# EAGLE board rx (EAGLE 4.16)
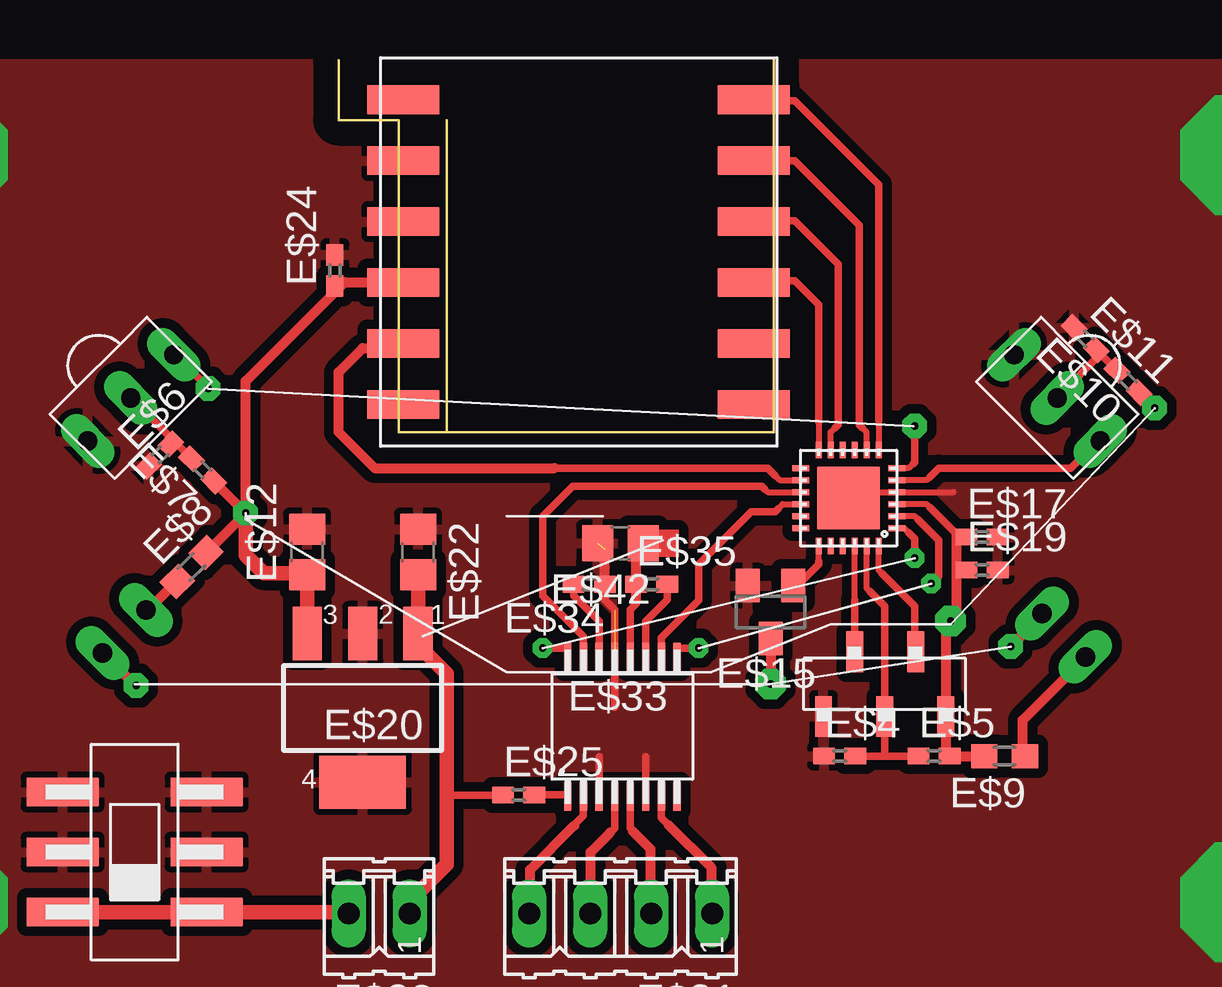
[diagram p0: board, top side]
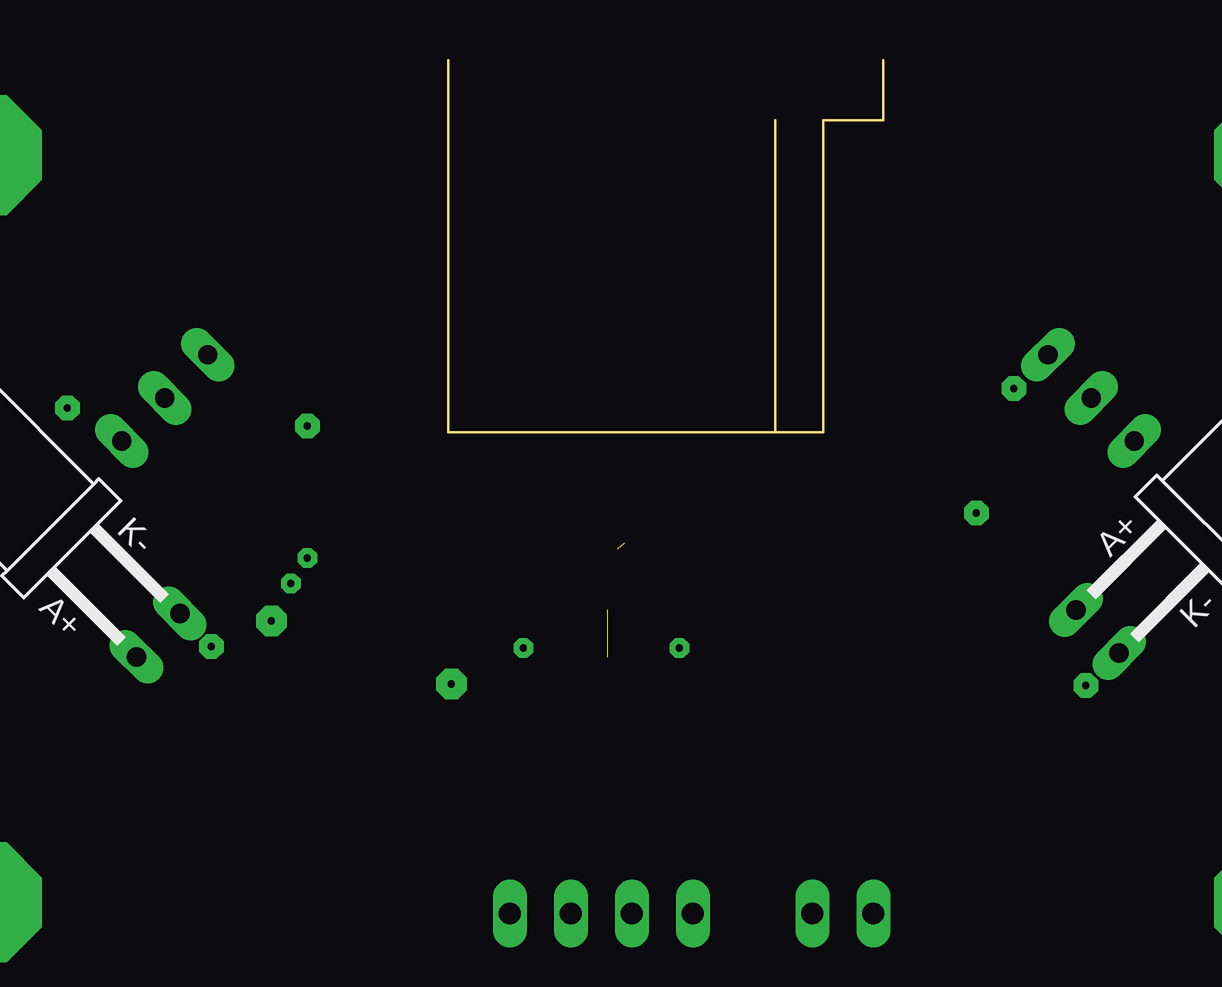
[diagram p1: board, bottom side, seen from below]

Size 18.12 x 15.5 mm. Coordinates in mm from the lower left corner, seen from the top.
Outline: 0,15.5 0,13 2.5,13 2.5,0 4.5,0
Outline: 4.5,0 18.12,0 18.12,15.5
Outline: 4.5,13 4.5,0
Copper layers (1*16): Top 0.035mm / dielectric 1.5mm / Bottom 0.035mm
Design rules "default": minimum track width 10mil, minimum drill 24mil, track to track 8mil, track to pad 8mil, pad to pad 8mil, via to via 8mil, smd to smd 8mil, copper to edge 40mil, drill to drill 8mil, minimum pad ring 10mil, minimum via ring 8mil, stop-mask expansion 4mil, vias tented up to drill 0mil, thermal gap 10mil

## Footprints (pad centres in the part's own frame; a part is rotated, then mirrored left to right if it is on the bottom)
QFN24 = smd 0.7 x 0.25: 1 -2,1.25; 2 -2,0.75; 3 -2,0.25; 4 -2,-0.25; 5 -2,-0.75; 6 -2,-1.25; 13 2,-1.25; 14 2,-0.75; 15 2,-0.25; 16 2,0.25; 17 2,0.75; 18 2,1.25 | smd 0.25 x 0.7: 7 -1.25,-2; 8 -0.75,-2; 9 -0.25,-2; 10 0.25,-2; 11 0.75,-2; 12 1.25,-2; 19 1.25,2; 20 0.75,2; 21 0.25,2; 22 -0.25,2; 23 -0.75,2; 24 -1.25,2 | smd 2.6 x 2.6: EP 0,0
ZETA-RF = smd 3 x 1.2: 1 -7.303,6.35; 2 -7.303,3.81; 3 -7.303,1.27; 4 -7.303,-1.27; 5 -7.303,-3.81; 6 -7.303,-6.35; 7 7.303,-6.35; 8 7.303,-3.81; 9 7.303,-1.27; 10 7.303,1.27; 11 7.303,3.81; 12 7.303,6.35
HEADER5S = smd 0.7 x 1.7: P$1 0,1.35; P$2 2.55,1.35; P$3 -2.55,1.35; P$4 -1.3,-1.35; P$5 1.25,-1.35
C0402 = smd 0.9 x 0.7: 1 -0.65,0; 2 0.65,0
R0603 = smd 1.1 x 1: 1 -0.85,0; 2 0.85,0
C0805 = smd 1.3 x 1.5: 1 -0.95,0; 2 0.95,0
TSOP32238 = drill 0.8 long: P$1 -2.54,0; P$2 0,0; P$3 2.54,0
SOT23 = smd 1 x 1.4: 1 -0.95,-1.1; 2 0.95,-1.1; 3 0,1.1
LED_T1 = drill 0.813 long: A -1.27,-6.35; K 1.27,-6.35
SOT223 = smd 1.219 x 2.235: 1 -2.311,-3.099; 2 0,-3.099; 3 2.311,-3.099 | smd 3.6 x 2.2: 4 0,3.099
04P = drill 0.914 long: 1 -3.81,0; 2 -1.27,0; 3 1.27,0; 4 3.81,0
02P = drill 0.914 long: 1 -1.27,0; 2 1.27,0
SLIDER5 = smd 1.2 x 3: P$1 0,3; P$2 2.5,3; P$3 -2.5,3; P$4 -2.5,-3; P$5 0,-3; P$6 2.5,-3
PW16 = smd 0.3 x 1.2: 1 0,-2.9; 2 0.65,-2.9; 3 1.3,-2.9; 4 1.95,-2.9; 5 2.6,-2.9; 6 3.25,-2.9; 7 3.9,-2.9; 8 4.55,-2.9; 13 4.55,2.9; 14 3.9,2.9; 15 3.25,2.9; 16 2.6,2.9; 17 1.95,2.9; 18 1.3,2.9; 19 0.65,2.9; 20 0,2.9

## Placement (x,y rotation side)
E$1  [QFN24]  21.25,-2.75 180 top
E$2  [ZETA-RF]  10,7.5 0 top
E$3  [HEADER5S]  not placed on the board
E$4  [C0402]  not placed on the board
E$5  [C0402]  not placed on the board
E$6  [C0402]  not placed on the board
E$7  [C0402]  not placed on the board
E$8  [R0603]  not placed on the board
E$9  [R0603]  not placed on the board
E$10  [C0402]  not placed on the board
E$11  [C0402]  not placed on the board
E$12  [C0805]  not placed on the board
E$13  [TSOP32238]  -8.66,1.42 45 top  (outside the outline)
E$14  [TSOP32238]  29.94,1.42 315 top  (outside the outline)
E$15  [SOT23]  not placed on the board
E$16  [LED_T1]  not placed on the board
E$17  [C0402]  not placed on the board
E$18  [LED_T1]  not placed on the board
E$19  [C0402]  not placed on the board
E$20  [SOT223]  not placed on the board
E$21  [04P]  not placed on the board
E$22  [C0805]  not placed on the board
E$23  [02P]  not placed on the board
E$24  [C0402]  -0.16,6.73 90 top
E$25  [C0402]  not placed on the board
E$26  [SLIDER5]  not placed on the board
E$33  [PW16]  not placed on the board
E$34  [C0402]  not placed on the board
E$35  [C0402]  not placed on the board
E$42  [C0805]  not placed on the board

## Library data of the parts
E$1 = freescale
E$2 = silabs
E$3 E$13 E$14 E$16 E$18 E$26 = sb
E$4-E$12 E$15 E$17 E$19 E$20 E$22 E$24 E$25 E$34 E$35 E$42 = ref-packages
E$21 E$23 = con-amp-quick
E$33 = TI_MSP430_v122

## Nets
GND: E$2.2 E$2.3 E$3.P$2 E$4.1 E$6.1 E$11.1 E$12.2 E$13.P$1 E$14.P$1 E$15.2 E$17.2 E$19.2 E$20.2 E$20.4 E$22.1 E$24.2 E$26.P$1 E$26.P$3 E$26.P$4 E$26.P$5 E$33.17 E$34.1 E$42.2
S$21: E$13.P$2
S$22: E$14.P$2

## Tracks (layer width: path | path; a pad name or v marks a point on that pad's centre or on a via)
GND  (via drill 0.6 pad 5)  (2 unrouted)
  Top 0.254: 22,-2.5 25.62,-2.5
  Top 0.305: 10.85,-13.53 10.85,-15.58 | 12.8,-13.53 12.8,-15.58 | 11.09,-6.83 11.09,-6.99 11.5,-7.4 11.5,-11.47
  Top 0.406: 11.09,-6.83 11.09,-4.88
  other vias: -16.28,-19.6 -16.28,11.54 37.56,-19.6 37.56,11.54
  pour Top (isolate 0.406): -20.03,-23.41 -20.03,15.35 41.37,15.35 41.37,-23.41
S$1
  Top 0.254: 20,0.44 20,-0.5
  Top 0.305: 18,6.31 19,6.31 20,5.31 20,0.44
S$2
  Top 0.254: 20.69,0.19 20.5,0 20.5,-0.5
  Top 0.305: 18,8.81 19,8.81 20.81,7 20.81,0.31 20.69,0.19
S$3
  Top 0.254: 21.81,0.19 22,0 22,-0.5
  Top 0.305: 18,11.31 19,11.31 21.69,8.62 21.69,0.31 21.81,0.19
S$4
  Top 0.254: 22.5,0.5 22.5,-0.5
  Top 0.305: 18,13.81 19,13.81 22.5,10.31 22.5,0.5
S$5
  Top 0.254: 18.19,-1.81 18.38,-2 19,-2
  Top 0.305: 9,-1.5 17.88,-1.5 18.19,-1.81
  Top 0.406: 1.5,3.5 1,3.5 0,2.5 0,0 1.5,-1.5 9,-1.5
S$6
  Top 0.254: 22.12,-6.62 22,-6.5 22,-5
  Top 0.305: 22.75,-13.5 22.75,-7.25 22.12,-6.62
S$7
  Top 0.254: 21.5,-7 21.5,-5
  Top 0.305: 21.5,-8.75 21.5,-7
S$8
  Top 0.254: 22.62,-5.88 22.5,-5.75 22.5,-5
  Top 0.305: 22.62,-5.88 24,-7.25 24,-8.75
S$9
  Top 0.305: 21.75,-13.5 23.75,-13.5
S$10
  Top 0.254: 23.5,-2 24.5,-2 24.62,-1.88 | 31.5,-0.5 31.56,-0.5
  Top 0.305: 24.62,-1.88 25,-1.5 30.5,-1.5 31.5,-0.5
S$11  (via drill 0.3 pad 1.02)
  other vias: 24,0.25
S$12
  Top 0.254: 17.75,-2.38 17.88,-2.5 19,-2.5
  Top 0.305: 10.19,-9.69 10.19,-8.5 8.5,-6.81 8.5,-3.5 9.75,-2.25 17.62,-2.25 17.75,-2.38
S$13
  Top 0.61: 3,-19.5 4.5,-18 4.5,-10.06 3.5,-9.06
S$14
  Top 0.406: 18,-9.19 18,-10.44
S$15
  Top 0.406: 28,-8.94 29.37,-7.53
S$16
  Top 0.254: 24.62,-3.12 24.5,-3 23.5,-3
  Top 0.305: 25.75,-4.25 24.62,-3.12
  Top 0.406: 25.75,-4.25 25.75,-7.62 25.31,-8.06 25.31,-13.56
S$17
  Top 0.254: 18.31,-3.19 18.5,-3 19,-3
  Top 0.305: 13.44,-9 13.44,-8.56 15,-7 15,-5.5 17.19,-3.31 18.19,-3.31 18.31,-3.19
S$18
  Top 0.305: 14.12,-9 15,-9
S$19
  Top 0.305: 8.5,-9 9.5,-9
S$20  (via drill 0.3 pad 0.81)
  other vias: 24.69,-6.31
S$21
  Top 0.305: E$13.P$2 -6.35,-0.89
S$22
  Top 0.305: E$14.P$2 31.87,3.39
S$23
  Top 0.254: 23.5,-4 23.56,-4 23.75,-4.19
  Top 0.305: 24,-5.25 24,-4.44 23.75,-4.19
S$24
  Top 0.254: 24.12,-3.62 24,-3.5 23.5,-3.5 | 25,-6 24.69,-6.31
  Top 0.305: 24.12,-3.62 25,-4.5 25,-6
S$25
  Top 0.254: 23.5,-1.5 23.75,-1.5 23.94,-1.31
  Top 0.305: 24,0.25 24,-1.25 23.94,-1.31
S$26
  Top 0.305: -5.47,1.88 -6.76,3.17
S$27
  Top 0.406: -9.8,-9.22 -8.45,-10.57
S$28  (via drill 0.3 pad 1.02)
  other vias: 28,-8.94
S$29  (via drill 0.3 pad 0.81)
  other vias: 24,-5.25
S$30  (via drill 0.3 pad 0.81)
  other vias: 15,-9
S$31  (via drill 0.3 pad 0.81)
  other vias: 8.5,-9
S$32
  Top 0.254: 20,-5.38 20,-5
  Top 0.305: 20,-5.38 20,-5.5 19,-6.5
S$33
  Top 0.406: 28.5,-13.5 28.5,-12 31,-9.5
S$34  (via drill 0.3 pad 1.27)
  other vias: 18,-10.5
S$35  (via drill 0.3 pad 1.02)
  Top 0.305: v34,1 33.5,1.5
S$36
  Top 0.406: -5.06,-2.19 -3.88,-3.38 -5.5,-5
  Top 0.61: -1.31,-7.38 -1.31,-5.88 -3.12,-5.88 -3.88,-5.12 -3.88,-3.38
S$37  (via drill 0.3 pad 1.02)
  other vias: -8.44,-10.56
S$38
  Top 0.406: -8.03,-7.47 -6.76,-6.24
S$39
  Top 0.406: 25.5,-13.5 27,-13.5
S$40  (via drill 0.3 pad 1.02)
  other vias: -3.88,-3.38
S$41  (via drill 0.3 pad 1.02)
  other vias: -5.44,1.81
S$42
  Top 0.305: 31.75,3.25 32.25,2.75
S$43  (via drill 0.3 pad 1.27)
  other vias: 25.5,-7.88
S$45
  Top 0.406: 2.25,6.25 0.25,6.25 -3.88,2.12 -3.88,-3.38
S$46
  Top 0.305: 4.5,-15.12 6.5,-15.12
S$48
  Top 0.61: 3.31,-6.12 3.31,-8.12
S$49
  Top 0.61: -11,-20 0.5,-20
S$90
  Top 0.305: 12.27,-16.65 12.15,-16.52 12.15,-15.53
  Top 0.406: 13,-20 13,-17.38 12.27,-16.65
S$91
  Top 0.305: 11.31,-16.69 11.5,-16.5 11.5,-15.53
  Top 0.406: 10.5,-20.01 10.5,-17.5 11.31,-16.69
S$92
  Top 0.305: 9.82,-16.39 9.8,-16.39 10.2,-15.99 10.2,-15.53
  Top 0.406: 9.82,-16.39 7.98,-18.23 7.98,-20.04
S$97
  Top 0.305: 12.39,-6.99 12.39,-7.16 12.15,-7.4 12.15,-9.03
  Top 0.406: 12.39,-4.72 12.39,-5.45 12.39,-6.99
S$98
  Top 0.305: 10.85,-9.19 10.85,-7.89 9.79,-6.83 9.79,-6.18
S$99
  Top 0.305: 13.69,-6.26 13.69,-6.99 12.8,-7.89 12.8,-8.86
S$100
  Top 0.305: 13.45,-15.53 13.45,-16.07 13.76,-16.39
  Top 0.406: 15.54,-20 15.54,-19.17 15.54,-18.16 13.76,-16.39
S$102
  Top 0.305: 8.49,-15.12 9.47,-15.12
(copper drawn outside any net)
  shapes: Top area x1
